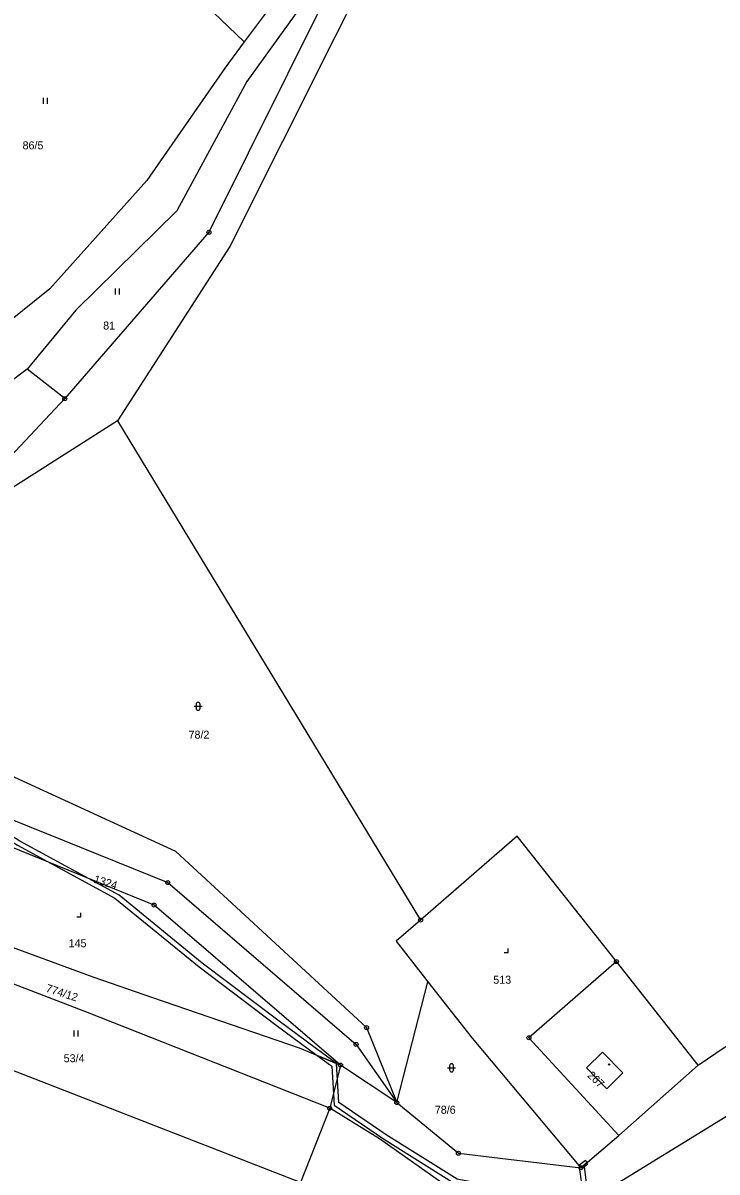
# Model space of a CAD drawing. Extents: x -745926 to -742978, y -968282 to -965689.
# Drawn here: x -743844.3 to -743757.5, y -967299.8 to -967156.2 of the extents above; entities that cross this region are included whole.
import ezdxf

# ---------------------------------------------------------------- set-up
doc = ezdxf.new("R2010")
doc.units = 0
for name, color, linetype in [('Hranice parcel', 7, 'Continuous'), ('Parcelní čísla', 7, 'Continuous'), ('Vnitřní kresba', 7, 'Continuous'), ('Věcná břemena k části', 7, 'Continuous'), ('Značky bodu BP', 7, 'Continuous'), ('Značky budov', 7, 'Continuous'), ('Značky kultur', 7, 'Continuous')]:
    doc.layers.add(name, color=color, linetype=linetype)

msp = doc.modelspace()

# ---------------------------------------------------------------- linework, layer by layer
at = {"layer": 'Hranice parcel'}
for p, q in [((-743843.76, -967132.47), (-743816.66, -967158.58)), ((-743804.7, -967142.45), (-743816.66, -967158.58)), ((-743839.11, -967203.15), (-743843.8, -967199.45)), ((-743832.51, -967205.94), (-743794.61, -967268.32)), ((-743827.93, -967266.44), (-743847.24, -967258.63)), ((-743804.62, -967286.45), (-743827.93, -967266.44)), ((-743759.88, -967286.47), (-743770.12, -967273.51)), ((-743759.88, -967286.47), (-743742.28, -967274.4)), ((-743797.58, -967291.13), (-743793.69, -967276.04)), ((-743809.64, -967301.14), (-743866.31, -967279.05)), ((-743804.62, -967286.45), (-743805.97, -967291.84)), ((-743797.58, -967291.13), (-743804.62, -967286.45)), ((-743769.8, -967295.24), (-743759.88, -967286.47)), ((-743805.97, -967291.84), (-743809.64, -967301.14)), ((-743774.56, -967299.28), (-743769.8, -967295.24))]:
    msp.add_line(p, q, dxfattribs=at)
for points in [[(-743720.86, -967060.04), (-743759.25, -967102.69), (-743798.69, -967144.72), (-743818.48, -967184.16), (-743832.51, -967205.94)], [(-743801.35, -967142.75), (-743816.35, -967163.51), (-743825.1, -967179.69), (-743837.73, -967192.1), (-743843.8, -967199.45)], [(-743801.35, -967142.75), (-743821.07, -967182.36), (-743839.11, -967203.15)], [(-743816.66, -967158.58), (-743819.1, -967161.86), (-743828.83, -967175.91), (-743840.97, -967189.42), (-743847.85, -967194.95)], [(-743843.8, -967199.45), (-743856.61, -967209.05), (-743868.26, -967215.5)], [(-743839.11, -967203.15), (-743850.9, -967215.67), (-743867.24, -967241.32)], [(-743832.51, -967205.94), (-743849.44, -967216.68), (-743858.27, -967237.64), (-743846.94, -967249.76), (-743825.25, -967259.7), (-743801.35, -967281.76), (-743797.58, -967291.13)], [(-743867.24, -967241.32), (-743845.71, -967255.74), (-743826.22, -967263.63), (-743802.67, -967283.86), (-743797.58, -967291.13)], [(-743770.12, -967273.51), (-743782.53, -967257.82), (-743794.61, -967268.32)], [(-743860.57, -967266.24), (-743835.61, -967275.4), (-743828.13, -967277.99), (-743809.78, -967284.3), (-743804.62, -967286.45)], [(-743794.61, -967268.32), (-743797.66, -967270.97), (-743793.69, -967276.04)], [(-743805.97, -967291.84), (-743836.25, -967279.89), (-743865.22, -967268.75)], [(-743770.12, -967273.51), (-743781.05, -967283.03), (-743769.8, -967295.24)], [(-743793.69, -967276.04), (-743788.16, -967283.08), (-743774.56, -967299.28)], [(-743797.58, -967291.13), (-743789.87, -967297.47), (-743774.56, -967299.28)], [(-743754.93, -967292), (-743773.22, -967303.26), (-743791.24, -967301.66), (-743799.74, -967295.65), (-743805.97, -967291.84)]]:
    msp.add_lwpolyline(points, dxfattribs=at)
at = {"layer": 'Vnitřní kresba'}
for p, q in [((-743773.87, -967286.79), (-743771.87, -967284.82)), ((-743771.87, -967284.82), (-743769.31, -967287.43)), ((-743771.31, -967289.4), (-743773.87, -967286.79)), ((-743769.31, -967287.43), (-743771.31, -967289.4))]:
    msp.add_line(p, q, dxfattribs=at)
at = {"layer": 'Věcná břemena k části'}
for points in [[(-743807.54, -967285.23), (-743805.11, -967286.25), (-743807.64, -967284.42), (-743812.3, -967280.97), (-743821.91, -967273.69), (-743832.28, -967265.22), (-743844.72, -967258.44), (-743851.93, -967253.92), (-743858.53, -967249.1), (-743865.06, -967245.53), (-743867.13, -967244.73), (-743867.11, -967245.38), (-743865.32, -967246.07), (-743858.86, -967249.6), (-743852.27, -967254.42), (-743845.02, -967258.96), (-743832.86, -967265.59), (-743822.29, -967274.15), (-743812.66, -967281.45)], [(-743779.92, -967302.66), (-743773.63, -967302.93), (-743774.1, -967299.11), (-743773.67, -967298.77), (-743773.78, -967298.62), (-743774.56, -967299.28), (-743774.77, -967299.26), (-743774.31, -967302.31), (-743783.74, -967301.9), (-743790.04, -967300.71), (-743798.92, -967295.18), (-743804.82, -967291.12), (-743805.11, -967286.25), (-743807.54, -967285.23), (-743805.69, -967286.57), (-743805.4, -967291.44), (-743799.24, -967295.68), (-743790.26, -967301.28), (-743785.6, -967302.16)], [(-743774.56, -967299.28), (-743773.78, -967298.62), (-743773.99, -967298.35), (-743774.81, -967298.98)]]:
    msp.add_lwpolyline(points, close=True, dxfattribs=at)
at = {"layer": 'Značky bodu BP'}
for centre, radius in [((-743821.07, -967182.36), 0.25), ((-743821.07, -967182.36), 0.0152), ((-743839.11, -967203.15), 0.25), ((-743839.11, -967203.15), 0.0152), ((-743826.22, -967263.63), 0.25), ((-743826.22, -967263.63), 0.0152), ((-743827.93, -967266.44), 0.25), ((-743827.93, -967266.44), 0.0152), ((-743794.61, -967268.32), 0.25), ((-743794.61, -967268.32), 0.0152), ((-743770.12, -967273.51), 0.25), ((-743770.12, -967273.51), 0.0152), ((-743801.35, -967281.76), 0.25), ((-743801.35, -967281.76), 0.0152), ((-743781.05, -967283.03), 0.25), ((-743802.67, -967283.86), 0.25), ((-743802.67, -967283.86), 0.0152), ((-743781.05, -967283.03), 0.0152), ((-743804.62, -967286.45), 0.25), ((-743804.62, -967286.45), 0.0152), ((-743797.58, -967291.13), 0.25), ((-743797.58, -967291.13), 0.0152), ((-743805.97, -967291.84), 0.25), ((-743805.97, -967291.84), 0.0152), ((-743789.87, -967297.47), 0.25), ((-743789.87, -967297.47), 0.0152), ((-743774.56, -967299.28), 0.25), ((-743774.56, -967299.28), 0.0152)]:
    msp.add_circle(centre, radius, dxfattribs=at)
at = {"layer": 'Značky budov'}
msp.add_circle((-743771.02, -967286.38), 0.0875, dxfattribs=at)
at = {"layer": 'Značky kultur'}
for p, q in [((-743841.78, -967166.33), (-743841.78, -967165.58)), ((-743841.28, -967166.33), (-743841.28, -967165.58)), ((-743832.77, -967190.15), (-743832.77, -967189.4)), ((-743832.27, -967190.15), (-743832.27, -967189.4)), ((-743822.93, -967241.6), (-743821.93, -967241.6)), ((-743822.68, -967241.35), (-743822.68, -967241.85)), ((-743822.18, -967241.85), (-743822.18, -967241.35)), ((-743837.6, -967267.9), (-743837.1, -967267.9)), ((-743837.1, -967267.9), (-743837.1, -967267.4)), ((-743784.16, -967272.39), (-743783.66, -967272.39)), ((-743783.66, -967272.39), (-743783.66, -967271.89)), ((-743837.92, -967282.86), (-743837.92, -967282.11)), ((-743837.42, -967282.86), (-743837.42, -967282.11)), ((-743791.23, -967286.79), (-743790.23, -967286.79)), ((-743790.98, -967286.54), (-743790.98, -967287.04)), ((-743790.48, -967287.04), (-743790.48, -967286.54))]:
    msp.add_line(p, q, dxfattribs=at)
for centre, start, end in [((-743822.43, -967241.35), 0, 180), ((-743822.43, -967241.85), 180, 359.9879), ((-743790.73, -967286.54), 0, 180), ((-743790.73, -967287.04), 180, 359.9879)]:
    msp.add_arc(centre, 0.25, start, end, dxfattribs=at)

# ---------------------------------------------------------------- texts
at = {"layer": 'Parcelní čísla'}
for s, p in [('86/5', (-743844.38, -967172)), ('81', (-743834.3, -967194.52)), ('78/2', (-743823.62, -967245.65)), ('145', (-743838.62, -967271.72)), ('513', (-743785.51, -967276.28)), ('53/4', (-743839.24, -967286.09)), ('78/6', (-743792.82, -967292.53))]:
    msp.add_text(s, height=1, dxfattribs=at).set_placement(p)
for s, rotation, p in [('1324', 343, (-743835.56, -967263.63)), ('774/12', 342, (-743841.55, -967277.25)), ('267', 317, (-743773.82, -967287.84))]:
    msp.add_text(s, height=1, rotation=rotation, dxfattribs=at).set_placement(p)

doc.saveas('drawing.dxf')
